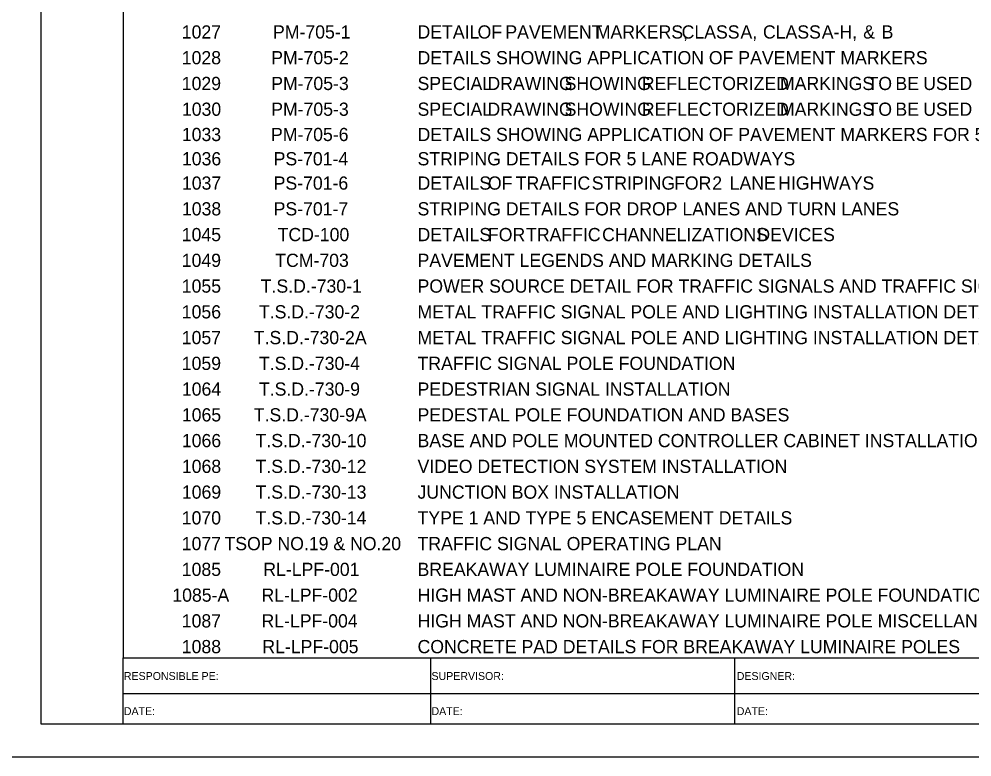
# Model space of a CAD drawing. Extents: x -12822 to 16384, y -6351 to 1913.
# Drawn here: x -804 to -82, y -3350 to -2791 of the extents above; entities that cross this region are included whole.
import ezdxf

# ---------------------------------------------------------------- set-up
doc = ezdxf.new("R2010")
doc.units = 0
for name, color, linetype in [('ANNO-TXT', 7, 'Continuous'), ('Level 10', 7, 'Continuous'), ('Level 62', 7, 'Continuous'), ('SHT-BDR', 7, 'Continuous'), ('SHT-BNDRY', 7, 'Continuous')]:
    doc.layers.add(name, color=color, linetype=linetype)

msp = doc.modelspace()

# ---------------------------------------------------------------- linework, layer by layer
at = {"layer": 'Level 62'}
msp.add_lwpolyline([(-850.02, -3349.9), (849.98, -3349.9), (849.98, -2249.9), (-850.02, -2249.9)], close=True, dxfattribs=at)
at = {"layer": 'SHT-BDR'}
msp.add_lwpolyline([(-725.04, -3274.85), (774.96, -3274.85), (774.96, -2324.85), (-725.04, -2324.85)], close=True, dxfattribs=at)
at = {"layer": 'SHT-BNDRY'}
for p, q in [((-725.04, -3324.9), (-725.04, -3274.85)), ((-492.43, -3274.85), (-492.43, -3324.9)), ((-261.71, -3324.9), (-261.71, -3274.85)), ((-725.04, -3301.85), (53.1, -3301.85))]:
    msp.add_line(p, q, dxfattribs=at)
msp.add_lwpolyline([(-787.52, -3324.9), (824.98, -3324.9), (824.98, -2274.9), (-787.52, -2274.9)], close=True, dxfattribs=at)

# ---------------------------------------------------------------- texts
at = {"layer": 'ANNO-TXT'}
for s, p in [('RESPONSIBLE PE:', (-724.57, -3291.63)), ('SUPERVISOR:', (-491.55, -3291.63)), ('DESIGNER:', (-260.33, -3291.63)), ('DATE:', (-724.57, -3318.22)), ('DATE:', (-491.55, -3318.22)), ('DATE:', (-260.33, -3318.22))]:
    msp.add_text(s, height=6, rotation=360, dxfattribs=at).set_placement(p)
at = {"layer": 'Level 10'}
for s, p in [('1027', (-680.71, -2805.93)), ('PM-705-1', (-611.6, -2805.93)), ('DETAIL', (-502.11, -2805.93)), (' OF', (-460.35, -2805.93)), (' PAVEMENT', (-439.31, -2805.93)), (' MARKERS,', (-370.83, -2805.93)), (' CLASS', (-305.79, -2805.93)), (' A,', (-261.23, -2805.93)), (' CLASS', (-244.19, -2805.93)), (' A-H,', (-199.63, -2805.93)), (' &', (-168.27, -2805.93)), (' B', (-154.27, -2805.93)), ('1028', (-680.71, -2825.43)), ('PM-705-2', (-612.96, -2825.43)), ('DETAILS SHOWING APPLICATION OF PAVEMENT MARKERS', (-502.11, -2825.43)), ('1029', (-680.71, -2844.93)), ('PM-705-3', (-612.96, -2844.93)), ('SPECIAL', (-502.11, -2844.93)), (' DRAWING', (-452.91, -2844.93)), (' SHOWING', (-394.43, -2844.93)), (' REFLECTORIZED', (-335.95, -2844.93)), (' MARKINGS', (-231.31, -2844.93)), (' TO', (-164.99, -2844.93)), (' BE', (-143.87, -2844.93)), (' USED', (-122.83, -2844.93)), ('1030', (-680.59, -2864.43)), ('PM-705-3', (-612.96, -2864.43)), ('SPECIAL', (-502.11, -2864.43)), (' DRAWING', (-452.91, -2864.43)), (' SHOWING', (-394.43, -2864.43)), (' REFLECTORIZED', (-335.95, -2864.43)), (' MARKINGS', (-231.31, -2864.43)), (' TO', (-164.99, -2864.43)), (' BE', (-143.87, -2864.43)), (' USED', (-122.83, -2864.43)), ('1033', (-680.66, -2883.57)), ('PM-705-6', (-613.13, -2883.57)), ('DETAILS SHOWING APPLICATION OF PAVEMENT MARKERS FOR 5-LANE ROADWAYS', (-502.11, -2883.57)), ('1036', (-680.59, -2901.96)), ('PS-701-4', (-611.12, -2901.96)), ('STRIPING DETAILS FOR 5 LANE ROADWAYS', (-502.11, -2901.96)), ('1037', (-680.59, -2920.36)), ('PS-701-6', (-611.12, -2920.36)), ('DETAILS', (-502.11, -2920.36)), (' OF', (-452.51, -2920.36)), (' TRAFFIC', (-431.47, -2920.36)), (' STRIPING', (-373.87, -2920.36)), (' FOR', (-311.47, -2920.36)), (' 2', (-282.59, -2920.36)), (' LANE', (-269.39, -2920.36)), (' HIGHWAYS', (-232.67, -2920.36)), ('1038', (-680.59, -2939.86)), ('PS-701-7', (-611.12, -2939.86)), ('STRIPING DETAILS FOR DROP LANES AND TURN LANES', (-502.11, -2939.86)), ('1045', (-680.71, -2959.36)), ('TCD-100', (-608.08, -2959.36)), ('DETAILS', (-502.11, -2959.36)), (' FOR', (-452.51, -2959.36)), (' TRAFFIC', (-423.63, -2959.36)), (' CHANNELIZATIONS', (-366.03, -2959.36)), (' DEVICES', (-248.43, -2959.36)), ('1049', (-680.71, -2978.86)), ('TCM-703', (-609.92, -2978.86)), ('PAVEMENT LEGENDS AND MARKING DETAILS', (-502.11, -2978.86)), ('1055', (-680.71, -2998.36)), ('T.S.D.-730-1', (-620.88, -2998.36)), ('POWER SOURCE DETAIL FOR TRAFFIC SIGNALS AND TRAFFIC SIGNAL POLES WITH LIGHTING', (-502.11, -2998.36)), ('1056', (-680.71, -3017.86)), ('T.S.D.-730-2', (-622.24, -3017.86)), ('METAL TRAFFIC SIGNAL POLE AND LIGHTING INSTALLATION DETAILS (SHEET 1 OF 2)', (-502.11, -3017.86)), ('1057', (-680.71, -3037.36)), ('T.S.D.-730-2A', (-626.16, -3037.36)), ('METAL TRAFFIC SIGNAL POLE AND LIGHTING INSTALLATION DETAILS (SHEET 2 OF 2)', (-502.11, -3037.36)), ('1059', (-680.71, -3056.86)), ('T.S.D.-730-4', (-622.24, -3056.86)), ('TRAFFIC SIGNAL POLE FOUNDATION', (-502.11, -3056.86)), ('1064', (-680.63, -3076.36)), ('T.S.D.-730-9', (-622.24, -3076.36)), ('PEDESTRIAN SIGNAL INSTALLATION', (-502.11, -3076.36)), ('1065', (-680.63, -3095.86)), ('T.S.D.-730-9A', (-626.16, -3095.86)), ('PEDESTAL POLE FOUNDATION AND BASES', (-502.11, -3095.86)), ('1066', (-680.63, -3115.36)), ('T.S.D.-730-10', (-624.8, -3115.36)), ('BASE AND POLE MOUNTED CONTROLLER CABINET INSTALLATIONS', (-502.11, -3115.36)), ('1068', (-680.63, -3134.86)), ('T.S.D.-730-12', (-624.8, -3134.86)), ('VIDEO DETECTION SYSTEM INSTALLATION', (-502.11, -3134.86)), ('1069', (-680.63, -3154.36)), ('T.S.D.-730-13', (-624.8, -3154.36)), ('JUNCTION BOX INSTALLATION', (-502.11, -3154.36)), ('1070', (-680.71, -3173.86)), ('T.S.D.-730-14', (-624.8, -3173.86)), ('TYPE 1 AND TYPE 5 ENCASEMENT DETAILS', (-502.11, -3173.86)), ('1077', (-680.71, -3193.36)), ('TSOP NO.19 & NO.20', (-648.36, -3193.36)), ('TRAFFIC SIGNAL OPERATING PLAN', (-502.11, -3193.36)), ('1085', (-680.71, -3212.86)), ('RL-LPF-001', (-618.96, -3212.86)), ('BREAKAWAY LUMINAIRE POLE FOUNDATION', (-502.11, -3212.86)), ('1085-A', (-687.87, -3232.36)), ('RL-LPF-002', (-620.32, -3232.36)), ('HIGH MAST AND NON-BREAKAWAY LUMINAIRE POLE FOUNDATIONS', (-502.11, -3232.36)), ('1087', (-680.71, -3251.86)), ('RL-LPF-004', (-620.32, -3251.86)), ('HIGH MAST AND NON-BREAKAWAY LUMINAIRE POLE MISCELLANEOUS DETAILS', (-502.11, -3251.86)), ('1088', (-680.71, -3271.36)), ('RL-LPF-005', (-619.66, -3271.36)), ('CONCRETE PAD DETAILS FOR BREAKAWAY LUMINAIRE POLES', (-502.11, -3271.36))]:
    msp.add_text(s, height=10, dxfattribs=at).set_placement(p)

doc.saveas('drawing.dxf')
